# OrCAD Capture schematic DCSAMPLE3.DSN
size A
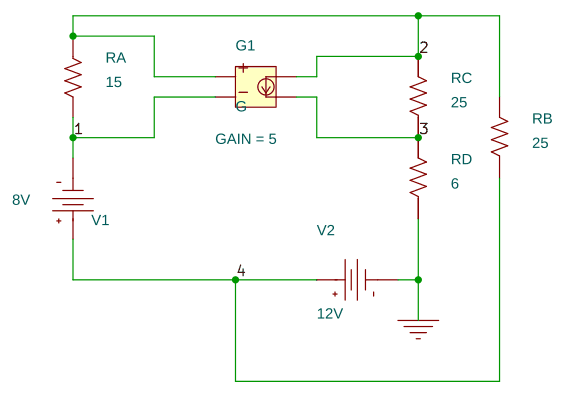
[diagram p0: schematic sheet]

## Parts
G1  G
RA  15  [AX/RC05]
RB  25  [AX/RC05]
RC  25  [AX/RC05]
RD  6  [AX/RC05]
V1  VDC
V2  VDC

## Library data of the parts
G1 = G: GAIN: 5
RA RB RC RD = R
V1 = VDC: DC: 8V
V2 = VDC: DC: 12V

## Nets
0: RD.1 V2.1(-)
1: G1.2 RA.2 V1.1(-)
2: G1.1 G1.3 RA.1 RB.2 RC.2
3: G1.4 RC.1 RD.2
4: RB.1 V1.0(+) V2.0(+)
